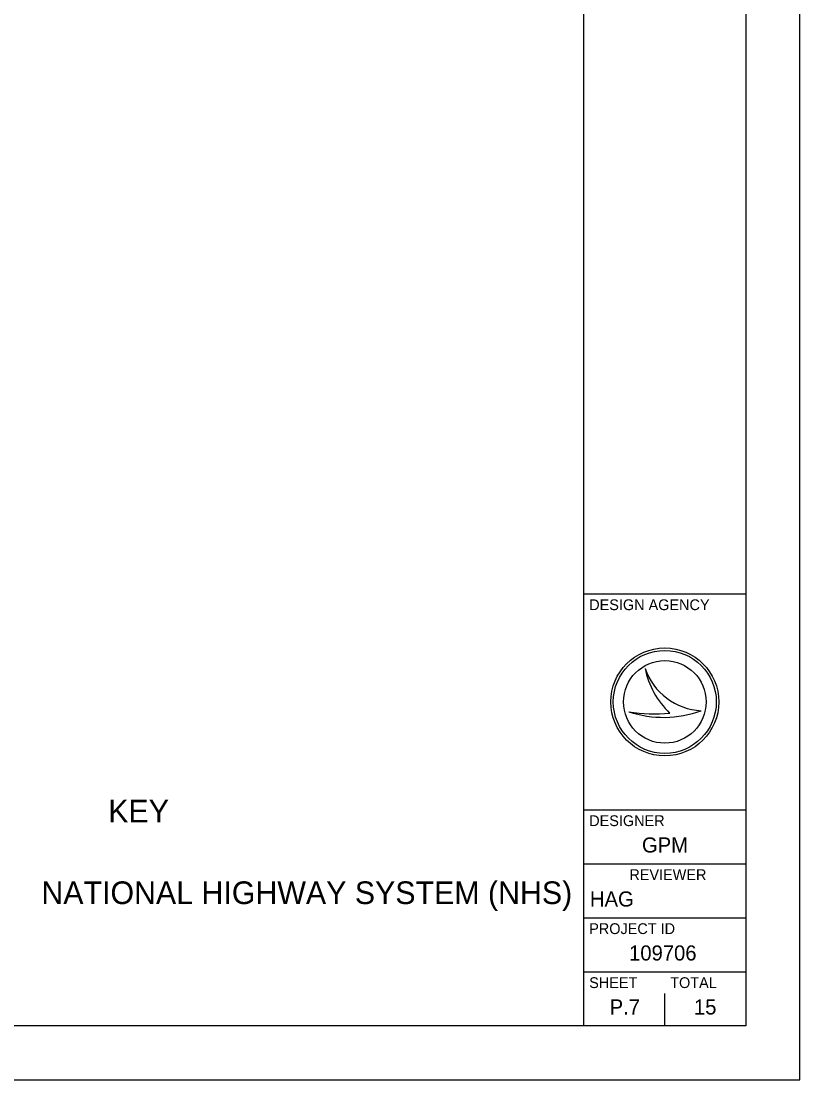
# Model space of a CAD drawing. Extents: x 2015843 to 2287843, y 623733 to 799733.
# Drawn here: x 2230169 to 2287843, y 623733 to 702171 of the extents above; entities that cross this region are included whole.
import ezdxf

# ---------------------------------------------------------------- set-up
doc = ezdxf.new("R2010")
doc.units = 0
for name, color, linetype in [('SH_Border', 7, 'Continuous'), ('SH_Cut_Line', 7, 'Continuous'), ('SH_Data', 7, 'Continuous'), ('UT_P_Electric', 7, 'Continuous')]:
    doc.layers.add(name, color=color, linetype=linetype)

msp = doc.modelspace()

# ---------------------------------------------------------------- linework, layer by layer
at = {"layer": 'SH_Border'}
for p, q in [((2271843, 627733), (2271843, 795733)), ((2271843, 659733), (2283843, 659733)), ((2271843, 643733), (2283843, 643733)), ((2271843, 639733), (2283843, 639733)), ((2271843, 635733), (2283843, 635733)), ((2271843, 631733), (2283843, 631733))]:
    msp.add_line(p, q, dxfattribs=at)
msp.add_lwpolyline([(2027843, 795733), (2283843, 795733), (2283843, 627733), (2027843, 627733)], close=True, dxfattribs=at)
at = {"layer": 'SH_Cut_Line'}
msp.add_lwpolyline([(2015843, 623733), (2287843, 623733), (2287843, 799733), (2015843, 799733)], close=True, dxfattribs=at)
at = {"layer": 'SH_Data'}
for p, q in [((2276383, 654210), (2276383, 654210)), ((2277843, 651733), (2277843, 651733)), ((2280541, 651081), (2280541, 651081)), ((2275180, 651009), (2275180, 651009)), ((2277843, 627733), (2277843, 630133)), ((2274843, 629133), (2274843, 629133))]:
    msp.add_line(p, q, dxfattribs=at)
for radius in [4000, 3814, 3814, 3058]:
    msp.add_circle((2277843, 651733), radius, dxfattribs=at)
for centre, radius, start, end in [((2280771, 655714), 4639, 198.92567, 198.93195), ((2282616, 655494), 6365, 191.63793, 191.64215), ((2280771, 655714), 4639, 198.93195, 267.16574), ((2282616, 655494), 6365, 191.64215, 226.09467), ((2277758, 658693), 8105, 251.45764, 290.08324), ((2277027, 660968), 10128, 259.49639, 259.49952), ((2277758, 658693), 8105, 251.45274, 251.45764), ((2277027, 660968), 10128, 259.49952, 276.66723)]:
    msp.add_arc(centre, radius, start, end, dxfattribs=at)

# ---------------------------------------------------------------- texts
for s, height, p in [('DESIGN AGENCY', 800, (2272243, 658533)), ('DESIGNER', 800, (2272243, 642533)), ('GPM', 1120, (2276150, 640573)), ('REVIEWER', 800, (2275218, 638533)), ('HAG', 1120, (2272297, 636573)), ('PROJECT ID', 800, (2272243, 634533)), ('109706', 1120, (2275196, 632573)), ('SHEET', 800, (2272243, 630533)), ('TOTAL', 800, (2278243, 630533)), ('P.7', 1120, (2273758, 628573)), ('15', 1120, (2280001, 628573))]:
    msp.add_text(s, height=height, dxfattribs=at).set_placement(p)
at = {"layer": 'UT_P_Electric'}
for s, p in [('KEY', (2236619, 642801)), ('NATIONAL HIGHWAY SYSTEM (NHS)', (2231666, 636755))]:
    msp.add_text(s, height=1680, dxfattribs=at).set_placement(p)

doc.saveas('drawing.dxf')
